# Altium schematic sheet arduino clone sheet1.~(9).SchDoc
size A; SheetNumber: 1; SheetTotal: 2
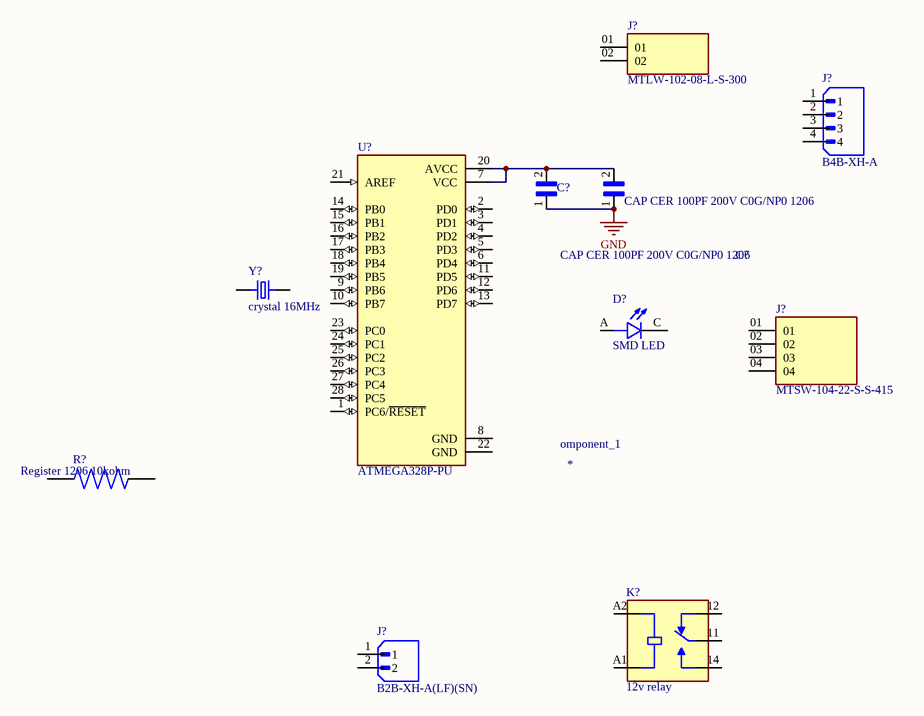
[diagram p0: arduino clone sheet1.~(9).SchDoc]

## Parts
(Parts that share a designator on the sheet are numbered #1, #2 ... from top to bottom, then left to right.)
*  omponent_1
C?#1  CAP CER 100PF 200V C0G/NP0 1206  [CAPC3216X88N]
C?#2  CAP CER 100PF 200V C0G/NP0 1206  [CAPC3216X88N]
D?  SMD LED  [LED_BR1102W-TR]
J?#1  MTLW-102-08-L-S-300  [SAMTEC_MTLW-102-08-L-S-300]
J?#2  B4B-XH-A  [JST_B4B-XH-A]
J?#3  MTSW-104-22-S-S-415  [SAMTEC_MTSW-104-22-S-S-415]
J?#4  B2B-XH-A(LF)(SN)  [JST_B2B-XH-A(LF)(SN)]
K?  12v relay  [RELAY_833H-1C-S-12VDC]
R?  Register 1206 10kohm  [RESC3015X65N]
U?  ATMEGA328P-PU  [DIP794W46P254L2967H457Q28B]
Y?  crystal 16MHz  [XTAL_ECS-160-20-5PX-TR]

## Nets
GND: C?#1.1 C?#2.1
NetC?#1_2: C?#1.2 C?#2.2 U?.7(VCC) U?.20(AVCC)

Not connected (* = marked no-connect by the designer): D? A C; J?#1 01 02; J?#2 1 2 3 4; J?#3 01 02 03 04; J?#4 1 2; K? 11(COM) 12(NC) 14(NO) A1(COIL2) A2(COIL1); R? 1 2; U? 1(PC6/~{RESET}) 2(PD0) 3(PD1) 4(PD2) 5(PD3) 6(PD4) 8(GND) 9(PB6) 10(PB7) 11(PD5) 12(PD6) 13(PD7) 14(PB0) 15(PB1) 16(PB2) 17(PB3) 18(PB4) 19(PB5) 21(AREF) 22(GND) 23(PC0) 24(PC1) 25(PC2) 26(PC3) 27(PC4) 28(PC5); Y? 1 2

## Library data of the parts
* = Component_1
C?#1 C?#2 = C1206C101J2GACTU
D? = BR1102W-TR: LED Uni-Color Red 660nm 2-Pin SMD T/R
J?#2 = B4B-XH-A: Connector Header Through Hole 4 position 0.098 (2.50mm); MF: JST Sales
J?#4 = B2B-XH-A(LF)(SN): Connector Header Through Hole 2 position 0.098 (2.50mm); MF: JST Sales
K? = 833H-1C-S-12VDC: 833H Series 10 A SPDT 12 VDC Through Hole Miniature Sugar Cube Power Relay; MF: Song Chuan
R? = Register 1206 10kohm: MP: RNCF1206BKY10K0
U? = ATMEGA328P-PU: ATmega Series 20 MHz 32 KB Flash 2 KB SRAM 8-Bit Microcontroller - DIP-28
Y? = ECS-160-20-5PX-TR: 16 MHz Â±30ppm Crystal 20pF 40 Ohms HC-49/US; MF: ECS Inc.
